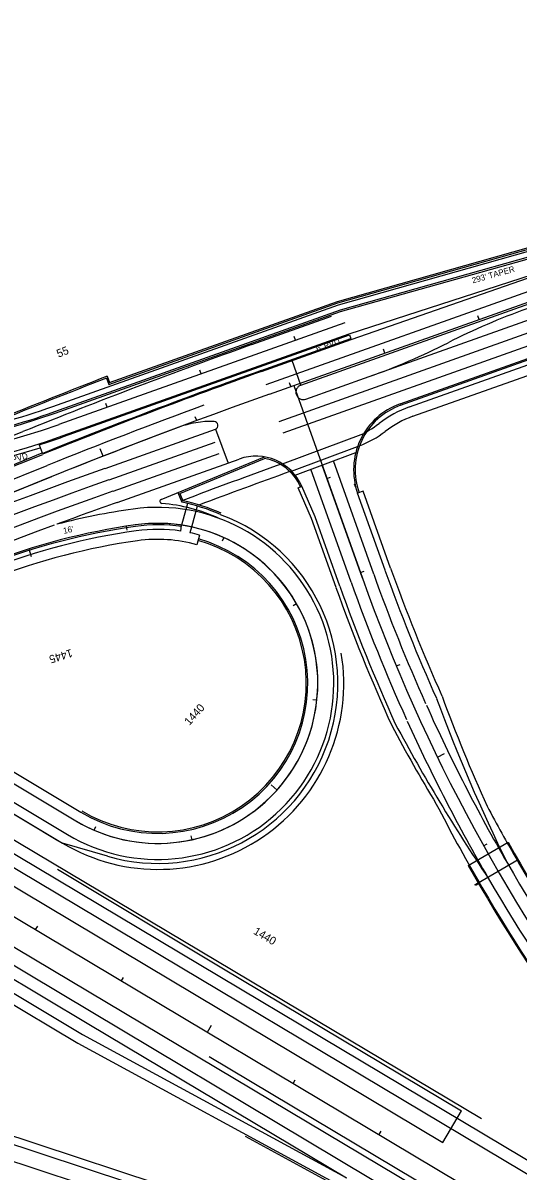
# Model space of a CAD drawing. Extents: x 2339272 to 2351734, y 366540 to 375057.
# Drawn here: x 2349780 to 2350276, y 367549 to 368697 of the extents above; entities that cross this region are included whole.
import ezdxf

# ---------------------------------------------------------------- set-up
doc = ezdxf.new("R2010")
doc.units = 0
for name, color, linetype in [('RD_HC_Cl', 7, 'Continuous'), ('RD_HC_CL_Rel', 7, 'Continuous'), ('RD_HC_Data_Tic', 7, 'Continuous'), ('RD_HC_Data_Tic_Rel', 7, 'Continuous'), ('RD_HC_TX_Rel_Sta50', 7, 'Continuous'), ('RD_HC_TX_Sta50', 7, 'Continuous'), ('RD_PD_Bridge', 7, 'Continuous'), ('RD_PD_ConcMed', 7, 'Continuous'), ('RD_PD_Final_LnLine', 7, 'Continuous'), ('RD_PD_Final_TrvlWay', 7, 'Continuous'), ('RD_PD_FOC', 7, 'Continuous'), ('RD_PD_GR', 7, 'Continuous'), ('RD_PD_GrRail', 7, 'Continuous'), ('RD_PD_NOISE-WALL-GM', 7, 'Continuous'), ('RD_PD_PaveShd', 7, 'Continuous'), ('RD_PD_SW', 7, 'Continuous')]:
    doc.layers.add(name, color=color, linetype=linetype)

msp = doc.modelspace()

# ---------------------------------------------------------------- linework, layer by layer
at = {"layer": 'RD_HC_Cl'}
for p, q in [((2346281.6, 369885.4), (2351112.4, 367003.2)), ((2350027, 368325.7), (2350990.3, 368668.5)), ((2350009.4, 368375.2), (2350089.1, 368403.6)), ((2350009.4, 368375.2), (2350089.1, 368403.6)), ((2350009.4, 368375.2), (2350089.1, 368403.6)), ((2350009.4, 368375.2), (2350089.1, 368403.6)), ((2350051.3, 368334.4), (2350119.9, 368141.7))]:
    msp.add_line(p, q, dxfattribs=at)
for centre, radius, start, end in [((2351947.8, 362927.7), 5782.1, 109.58804, 112.01473), ((2351947.8, 362927.7), 5782.1, 109.58804, 112.01473), ((2351947.8, 362927.7), 5782.1, 109.58804, 112.01473), ((2351947.8, 362927.7), 5782.1, 109.58804, 112.01473), ((2351947.8, 362927.7), 5729.6, 109.58804, 115.94073), ((2349555.5, 368844.5), 600, 245.9774, 292.0147), ((2349555.5, 368844.5), 600, 245.9774, 292.0147), ((2349555.5, 368844.5), 600, 245.9774, 292.0147), ((2349555.5, 368844.5), 600, 245.9774, 292.0147), ((2351779.9, 368732.5), 1762, 199.588, 235.1808)]:
    msp.add_arc(centre, radius, start, end, dxfattribs=at)
at = {"layer": 'RD_HC_CL_Rel'}
for p, q in [((2349816.7, 368295.5), (2350102.5, 368397.2)), ((2349328.8, 368200.1), (2349833.3, 367899.1))]:
    msp.add_line(p, q, dxfattribs=at)
for centre, radius, start, end in [((2349557.9, 369022.8), 772, 245.8825, 289.588), ((2349988.4, 367521.7), 680, 98.078, 111.0317), ((2349915.3, 368036.5), 160, 348.6282, 98.078), ((2349915.3, 368036.5), 160, 239.1785, 348.6282)]:
    msp.add_arc(centre, radius, start, end, dxfattribs=at)
at = {"layer": 'RD_HC_Data_Tic'}
for p, q in [((2350236.6, 368400.3), (2350235.3, 368404.1)), ((2350142.4, 368366.8), (2350141.1, 368370.6)), ((2350048.2, 368333.3), (2350046.9, 368337.1)), ((2349954.2, 368299.3), (2349952.8, 368303)), ((2349860.7, 368263.7), (2349857.8, 368271.1)), ((2350084.4, 368241.5), (2350088.1, 368242.8)), ((2350117.9, 368147.3), (2350121.6, 368148.6)), ((2350153.8, 368053.9), (2350157.5, 368055.5)), ((2350194.9, 367962.8), (2350202.1, 367966.3)), ((2350241.1, 367874.1), (2350244.6, 367876.1)), ((2349793.1, 367790.3), (2349795.2, 367793.8)), ((2349879, 367739.1), (2349881.1, 367742.5)), ((2349964.9, 367687.9), (2349969, 367694.7)), ((2350050.8, 367636.6), (2350052.8, 367640.1)), ((2350136.6, 367585.4), (2350138.7, 367588.8))]:
    msp.add_line(p, q, dxfattribs=at)
at = {"layer": 'RD_HC_Data_Tic_Rel'}
for p, q in [((2350052.9, 368379.6), (2350051.6, 368383.3)), ((2349958.7, 368346), (2349957.4, 368349.8)), ((2349864.5, 368312.5), (2349863.2, 368316.3)), ((2349883.6, 368193.6), (2349884.2, 368189.6)), ((2349981.4, 368182.2), (2349979.7, 368178.6)), ((2349786.3, 368171), (2349788.7, 368163.3)), ((2350054.1, 368116), (2350050.7, 368114)), ((2350074.4, 368019.7), (2350070.4, 368020.2)), ((2350034.5, 367929.8), (2350028.6, 367935.1)), ((2349851.6, 367889.7), (2349853.2, 367893.4)), ((2349949.5, 367880.2), (2349948.7, 367884.1))]:
    msp.add_line(p, q, dxfattribs=at)
at = {"layer": 'RD_PD_Bridge'}
for p, q in [((2350225.6, 367854.5), (2350265.6, 367877.7)), ((2350235.5, 367837.1), (2350275.5, 367860.3))]:
    msp.add_line(p, q, dxfattribs=at)
msp.add_lwpolyline([(2350232.5, 367835.3), (2350235.5, 367837.1), (2350236, 367836.2), (2350233, 367834.5)], close=True, dxfattribs=at)
for radius, start, end in [(1740, 209.4445, 222.6246), (1738.9, 209.4445, 222.6246), (1785.1, 209.4615, 222.6075), (1784, 209.4611, 222.6079)]:
    msp.add_arc((2351779.9, 368732.5), radius, start, end, dxfattribs=at)
at = {"layer": 'RD_PD_ConcMed'}
for p, q in [((2349821.1, 368283.3), (2350106.9, 368385)), ((2350018.6, 368349.3), (2350108.2, 368381.2)), ((2350106.9, 368385), (2350108.2, 368381.2)), ((2349796.8, 368275), (2349797.7, 368272.2)), ((2349799.8, 368266.9), (2349800, 368266.5))]:
    msp.add_line(p, q, dxfattribs=at)
for centre, radius, start, end in [((2351947.8, 362927.7), 5754.6, 109.58804, 111.91571), ((2349557.9, 369022.8), 785, 287.713, 289.588)]:
    msp.add_arc(centre, radius, start, end, dxfattribs=at)
at = {"layer": 'RD_PD_Final_LnLine'}
for p, q in [((2348620.9, 368538.6), (2351133.9, 367039.3)), ((2350058.4, 368334.8), (2350443.3, 368471.8)), ((2348577.9, 368466.5), (2351090.9, 366967.2)), ((2350023.6, 368335.2), (2350388.3, 368464.9)), ((2350036.7, 368298.4), (2350492.9, 368460.8)), ((2350040.7, 368287.1), (2350497, 368449.5)), ((2349816.7, 368295.5), (2350102.5, 368397.2)), ((2350126.7, 368343.2), (2350288.1, 368400.6)), ((2350058.4, 368334.8), (2350049.7, 368359.3)), ((2350063.4, 368320.7), (2350126.7, 368343.2)), ((2349862.5, 368251.3), (2349972.9, 368290.6)), ((2349972.9, 368290.6), (2349985.5, 368256.8)), ((2349866.5, 368240), (2349972.5, 368277.7)), ((2349866.5, 368240), (2349972.5, 368277.7)), ((2350040, 368256.1), (2350121.2, 368286.3)), ((2349870.5, 368228.7), (2349976.7, 368266.5)), ((2350049.1, 368248.8), (2350115.1, 368273.4)), ((2350052.6, 368244.8), (2350113.3, 368267.3)), ((2349685.9, 368206.5), (2349804.8, 368254.4)), ((2350119.9, 368141.7), (2350079.6, 368254.8)), ((2350131.2, 368145.8), (2350090.9, 368259)), ((2349690.3, 368195.4), (2349809.3, 368243.3)), ((2350108.5, 368137.7), (2350068.4, 368250.7)), ((2349945.1, 368216.5), (2349939.1, 368194.7)), ((2349954.7, 368213.8), (2349948.9, 368192.7)), ((2349076.8, 368154.8), (2349846.3, 367695.8)), ((2349846.3, 367695.8), (2350103.9, 367542))]:
    msp.add_line(p, q, dxfattribs=at)
for centre, radius, start, end in [((2350509.1, 367779.8), 670, 109.588, 116.9345), ((2349902.1, 368974.4), 670, 289.588, 296.9345), ((2350060.9, 368327.7), 7.5, 110.0123, 289.588), ((2349557.9, 369022.8), 772, 245.8825, 289.588), ((2351947.8, 362927.7), 5741.6, 110.24005, 111.91571), ((2349968.9, 368203.4), 95, 88.3389, 110.5615), ((2349971.5, 368294.3), 4, 289.588, 88.3389), ((2351947.8, 362927.7), 5729.6, 110.56147, 111.91571), ((2351783.3, 362853.3), 5729.6, 109.58804, 115.94073), ((2351783.3, 362853.3), 5717.6, 109.588, 115.9407), ((2351783.3, 362853.3), 5705.6, 109.588, 115.9407), ((2351783.3, 362853.3), 5693.6, 110.2594, 115.9407), ((2351779.9, 368732.5), 1774, 199.588, 204.3708), ((2351779.9, 368732.5), 1762, 199.588, 235.1808), ((2351779.9, 368732.5), 1750, 199.588, 204.1544), ((2351779.9, 368732.5), 1750, 204.2189, 210.0316), ((2351779.9, 368732.5), 1774, 204.4286, 210.1344)]:
    msp.add_arc(centre, radius, start, end, dxfattribs=at)
at = {"layer": 'RD_PD_Final_TrvlWay'}
for p, q in [((2348626.9, 368549), (2350811.2, 367245.8)), ((2350098.1, 368408.4), (2350380.3, 368487.3)), ((2350106.5, 368385.9), (2350378.1, 368474)), ((2350108.5, 368380.2), (2350378.1, 368474)), ((2349812.7, 368306.8), (2350098.1, 368408.4)), ((2350157.6, 368316), (2350426.5, 368411.7)), ((2349820.8, 368284.2), (2350106.5, 368385.9)), ((2350018.9, 368348.3), (2350108.5, 368380.2)), ((2350018.9, 368348.3), (2350108.5, 368380.2)), ((2349681.4, 368217.7), (2349800.3, 368265.5)), ((2349874.5, 368217.4), (2349996.7, 368260.8)), ((2349918.7, 368220.4), (2350021.9, 368263)), ((2350072.6, 368202.9), (2350059.3, 368233.6)), ((2350111.8, 368236), (2350112.9, 368232.8)), ((2350142.5, 368149.8), (2350115.1, 368226.6)), ((2349328.8, 368200.1), (2349833.3, 367899.1)), ((2350097.2, 368133.7), (2350072.6, 368202.9)), ((2349320.6, 368186.4), (2349825.1, 367885.4)), ((2349178.3, 368080.3), (2349840.1, 367685.4)), ((2349186.9, 367768.1), (2350139.3, 367454)), ((2349185.3, 367751.7), (2350134.3, 367438.8)), ((2349840.1, 367685.4), (2350103.9, 367542))]:
    msp.add_line(p, q, dxfattribs=at)
for centre, radius, start, end in [((2351947.8, 362927.7), 5753.6, 109.58804, 111.91571), ((2351947.8, 362927.7), 5753.6, 109.58804, 111.91571), ((2349557.9, 369022.8), 760, 245.8825, 289.588), ((2350181.1, 368250), 70, 109.588, 199.588), ((2349557.9, 369022.8), 784, 245.8825, 289.588), ((2350013.4, 368213.7), 50, 23.4033, 109.588), ((2349919.4, 368218.5), 2, 109.588, 268.7054), ((2351783.3, 362853.3), 5693.6, 109.588, 110.2317), ((2349988.4, 367521.7), 696, 98.078, 104.473), ((2349915.3, 368036.5), 176, 239.1785, 98.078), ((2349903.4, 368038.8), 178.4, 65.7857, 84.8843), ((2349988.4, 367521.7), 680, 98.078, 111.0317), ((2349915.3, 368036.5), 160, 239.1785, 98.078), ((2351779.9, 368732.5), 1738, 199.588, 204.1451), ((2351779.9, 368732.5), 1786, 199.588, 204.3527), ((2351824, 368624.5), 1738, 200.3001, 206.2201), ((2351727.2, 368839.3), 1786, 208.1749, 213.95), ((2351779.9, 368732.5), 1750, 210.0316, 235.1808), ((2351779.9, 368732.5), 1774, 210.1344, 235.1808)]:
    msp.add_arc(centre, radius, start, end, dxfattribs=at)
at = {"layer": 'RD_PD_FOC'}
for p, q in [((2350098, 368409.9), (2350377.5, 368488.9)), ((2349812.2, 368308.2), (2350098, 368409.9)), ((2350158.1, 368314.6), (2350427, 368410.3)), ((2349680.8, 368219.1), (2349799.8, 368266.9)), ((2349937.3, 368226.4), (2350022.1, 368261.4)), ((2349937.3, 368226.4), (2349940.4, 368218.9))]:
    msp.add_line(p, q, dxfattribs=at)
for centre, radius, start, end in [((2350181.1, 368250), 68.5, 109.588, 199.588), ((2349557.9, 369022.8), 758.5, 273.6919, 289.588), ((2350013.4, 368213.7), 48.5, 23.4033, 79.7168), ((2349903.4, 368038.8), 183.9, 65.8276, 78.4023), ((2349915.3, 368036.5), 158.5, 81.4435, 98.078), ((2349988.4, 367521.7), 678.5, 98.078, 111.0317), ((2349915.3, 368036.5), 148.5, 239.1785, 74.2365)]:
    msp.add_arc(centre, radius, start, end, dxfattribs=at)
at = {"layer": 'RD_PD_GR'}
for p, q in [((2349622, 368036.8), (2349838.4, 367907.7)), ((2349590.5, 368013.7), (2349820, 367876.8))]:
    msp.add_line(p, q, dxfattribs=at)
msp.add_arc((2349915.3, 368036.5), 186, 239.1785, 9.3841, dxfattribs=at)
at = {"layer": 'RD_PD_GrRail'}
for p, q in [((2349759.8, 367887.1), (2350238.9, 367601.3)), ((2349966.5, 367663.6), (2350194.1, 367527.8)), ((2350098.2, 367531.5), (2350003.1, 367583.3))]:
    msp.add_line(p, q, dxfattribs=at)
at = {"layer": 'RD_PD_NOISE-WALL-GM'}
for p, q in [((2350094.9, 368418.4), (2350375.1, 368497.5)), ((2350095.4, 368417), (2350375.5, 368496.1)), ((2349866.2, 368335.4), (2350095.4, 368417)), ((2349867.1, 368337.3), (2350094.9, 368418.4)), ((2349863.9, 368341.6), (2349866.2, 368335.4)), ((2349864.8, 368343.6), (2349867.1, 368337.3))]:
    msp.add_line(p, q, dxfattribs=at)
for radius, start, end in [(5802.6, 111.03734, 112.22876), (5801.1, 111.05253, 112.22969)]:
    msp.add_arc((2351947.8, 362927.7), radius, start, end, dxfattribs=at)
at = {"layer": 'RD_PD_PaveShd'}
for p, q in [((2349797.7, 368272.2), (2349799.8, 368266.9)), ((2350055.7, 368232), (2350059.3, 368233.6)), ((2350068.9, 368201.4), (2350055.7, 368232)), ((2349935.4, 368227.2), (2349939.3, 368217.6)), ((2350120.8, 368228.6), (2350115.1, 368226.6)), ((2350148.1, 368151.8), (2350120.8, 368228.6)), ((2350093.5, 368132.3), (2350068.9, 368201.5)), ((2349612, 368042.8), (2349838.4, 367907.7)), ((2349573.3, 368023.9), (2349815.4, 367879.5)), ((2349506.9, 367991.4), (2350200.4, 367577.6)), ((2349475.2, 367949.7), (2350173.7, 367533)), ((2349417.9, 367925.7), (2349835.2, 367676.8)), ((2349865, 367863.7), (2349820, 367876.8)), ((2349814.9, 367850.7), (2349979.3, 367752.1)), ((2349242.3, 367758.2), (2350063.2, 367487.5)), ((2349979.3, 367752.1), (2350219.1, 367609.1)), ((2349835.2, 367676.8), (2350099.1, 367533.3)), ((2350200.4, 367577.6), (2350219.1, 367609.1))]:
    msp.add_line(p, q, dxfattribs=at)
for centre, radius, start, end in [((2349557.9, 369022.8), 788, 248.8572, 287.713), ((2349903.4, 368038.8), 182.4, 65.8276, 78.6522), ((2349915.3, 368036.5), 180, 253.7711, 69.5644), ((2349915.3, 368036.5), 150, 239.1785, 74.2365), ((2351779.9, 368732.5), 1732, 199.588, 204.1451), ((2351779.9, 368732.5), 1790, 199.588, 204.357), ((2351824, 368624.5), 1732, 200.2934, 204.234), ((2351727.2, 368839.3), 1790, 208.1706, 211.0569), ((2351779.9, 368732.5), 1784, 207.2417, 210.1252), ((2351779.9, 368732.5), 1740, 208.0744, 210.0811)]:
    msp.add_arc(centre, radius, start, end, dxfattribs=at)
at = {"layer": 'RD_PD_SW'}
for p, q in [((2350096, 368415), (2350376, 368494.2)), ((2349810.4, 368313.4), (2350096, 368415)), ((2350167, 368312.9), (2350424.5, 368404.6)), ((2350170.3, 368303.5), (2350427.9, 368395.2)), ((2349938.2, 368188.8), (2349939.1, 368194.7)), ((2349948.9, 368192.7), (2349947.4, 368187.1)), ((2349957.1, 368184.7), (2349954.4, 368175.1))]:
    msp.add_line(p, q, dxfattribs=at)
for centre, radius, start, end in [((2349557.9, 369022.8), 753, 273.6903, 289.588), ((2350203.9, 368209.3), 110, 109.588, 127.6719), ((2350203.9, 368209.3), 100, 109.588, 127.6719), ((2350081.6, 368367.6), 100, 290.669, 307.6719), ((2350081.6, 368367.6), 90, 298.3172, 307.6719), ((2351947.8, 362927.7), 5659.7, 109.7006, 110.7841), ((2351947.8, 362927.7), 5649.7, 109.655, 110.6381), ((2349988.4, 367521.7), 674, 98.078, 111.0317), ((2349915.3, 368036.5), 154, 81.4435, 98.078), ((2349915.3, 368036.5), 154, 74.2365, 77.9742), ((2349988.4, 367521.7), 664, 98.078, 111.0317), ((2349915.3, 368036.5), 144, 74.2365, 98.078)]:
    msp.add_arc(centre, radius, start, end, dxfattribs=at)

# ---------------------------------------------------------------- texts
at = {"layer": 'RD_HC_TX_Rel_Sta50'}
for s, rotation, p in [('1445', 197.2882, (2349828.6, 368071)), ('1440', 48.1721, (2349946.9, 367993.9))]:
    msp.add_text(s, height=8, rotation=rotation, dxfattribs=at).set_placement(p)
at = {"layer": 'RD_HC_TX_Sta50'}
for s, rotation, p in [('55', 21.3625, (2349816, 368362.1)), ('1440', 329.1785, (2350010.2, 367786.6))]:
    msp.add_text(s, height=8, rotation=rotation, dxfattribs=at).set_placement(p)
at = {"layer": 'RD_PD_Final_TrvlWay'}
for s, rotation, p in [("293' TAPER", 15.6232, (2350230.4, 368436.4)), ("6' PVD", 19.588, (2350074.7, 368368)), ("4' PVD", 16.3155, (2349762.2, 368254.6)), ("16'", 13.289, (2349821.4, 368185.9))]:
    msp.add_text(s, height=6, rotation=rotation, dxfattribs=at).set_placement(p)

doc.saveas('drawing.dxf')
